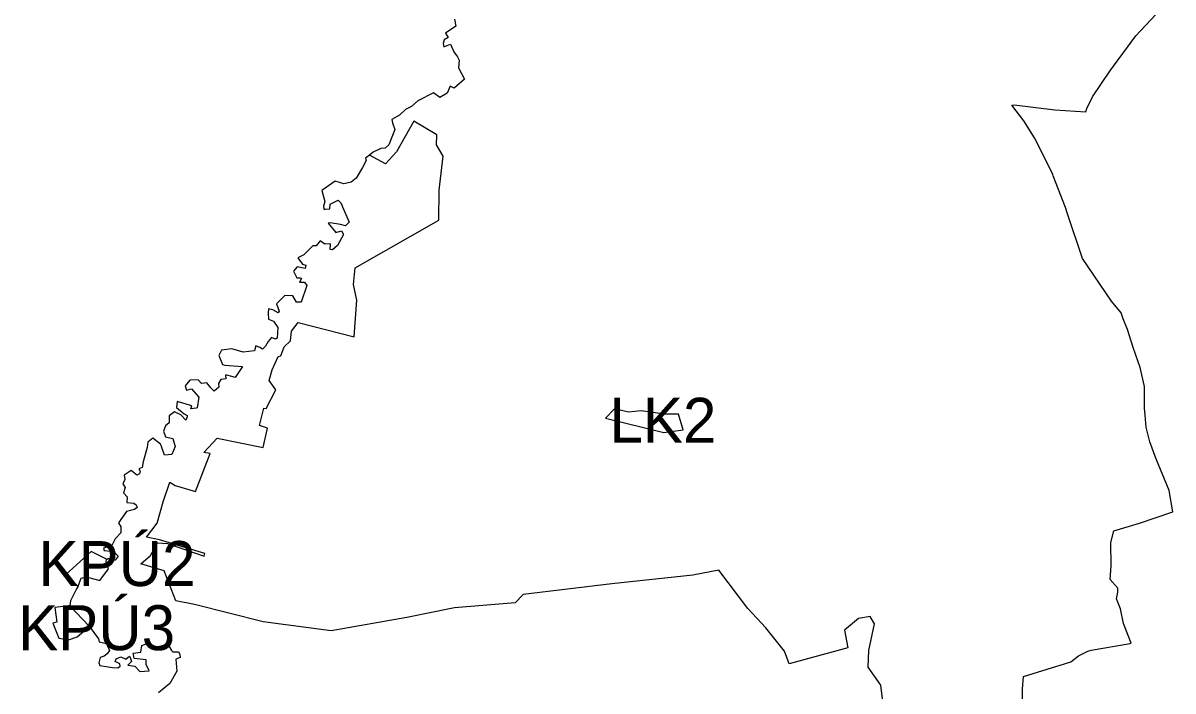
# Model space of a CAD drawing. Extents: x -744334 to -741989, y -1190045 to -1186328.
# Drawn here: x -744127 to -742592, y -1189155 to -1188264 of the extents above; entities that cross this region are included whole.
import ezdxf

# ---------------------------------------------------------------- set-up
doc = ezdxf.new("R2010")
doc.units = 0
for name, color, linetype in [('Hranice parcel', 7, 'Continuous'), ('Parcelní čísla', 7, 'Continuous'), ('Značky budov', 7, 'Continuous')]:
    doc.layers.add(name, color=color, linetype=linetype)

msp = doc.modelspace()

# ---------------------------------------------------------------- linework, layer by layer
at = {"layer": 'Hranice parcel'}
msp.add_line((-744038.9, -1189068.8), (-744064.9, -1189041.5), dxfattribs=at)
for points in [[(-743685.4, -1188682.5), (-743681.6, -1188633.9), (-743686.2, -1188613), (-743684.2, -1188590.5), (-743572.5, -1188526.8), (-743572, -1188487), (-743566.4, -1188441.6), (-743575.6, -1188426.2), (-743575, -1188413), (-743605.6, -1188394.6), (-743628.6, -1188435.9), (-743643.4, -1188451.8), (-743665, -1188440.3)], [(-742977.4, -1189187.5), (-742982, -1189147.7), (-742998.9, -1189123.5), (-742998.4, -1189101.1), (-742990.6, -1189065.5), (-742996.6, -1189055.9), (-743012.1, -1189058.4), (-743030.7, -1189074.1), (-743026.4, -1189097.8), (-743104.8, -1189118.8), (-743110.8, -1189101.9), (-743135.7, -1189071), (-743159.9, -1189045.2), (-743198.6, -1188994.2), (-743233.3, -1189000.5), (-743341.5, -1189012.1), (-743459.5, -1189026.3), (-743470.5, -1189037.6), (-743551.5, -1189044.5), (-743615, -1189057.1), (-743715.9, -1189075), (-743806.8, -1189063.1), (-743898.4, -1189039.9), (-743923.3, -1189034.9), (-743939.1, -1188994.9), (-743970.2, -1188985.6), (-743957.3, -1188974.4), (-743947.7, -1188957.5), (-743934.5, -1188958.5), (-743885.6, -1188975.4), (-743884.9, -1188971.7), (-743945.1, -1188953.5), (-743962.6, -1188949.9), (-743948.4, -1188931.3), (-743940.5, -1188902.9), (-743931.2, -1188876.4), (-743924.2, -1188881), (-743897.1, -1188889), (-743877.6, -1188838.4), (-743885.9, -1188837), (-743868, -1188817.8), (-743806.8, -1188830.4), (-743801.2, -1188804.3), (-743811.8, -1188801), (-743805.8, -1188777.8), (-743802.9, -1188778.1), (-743790, -1188753.3), (-743798.9, -1188741.1), (-743794.9, -1188726.8), (-743787, -1188709), (-743783.3, -1188708), (-743778.7, -1188696.1), (-743770.5, -1188687.8), (-743769.1, -1188675.2), (-743760.2, -1188663.6), (-743685.4, -1188682.5)], [(-744053.9, -1189015.5), (-744049.6, -1189004.7), (-744042.9, -1189002.8), (-744025, -1189007.6), (-744013.5, -1188992.2), (-744016.2, -1188983), (-744016, -1188979.4)]]:
    msp.add_lwpolyline(points, dxfattribs=at)
msp.add_lwpolyline([(-743349.7, -1188791.2), (-743271.8, -1188810.2), (-743245.9, -1188806.7), (-743252.5, -1188786), (-743270.8, -1188786), (-743302.1, -1188781.6), (-743319.1, -1188783), (-743337.6, -1188778.6)], close=True, dxfattribs=at)
at = {"layer": 'Parcelní čísla'}
for p, q in [((-742641.8, -1188280.9), (-742609, -1188245.6)), ((-743551.5, -1188258.5), (-743549.5, -1188268)), ((-743549.5, -1188268), (-743563.4, -1188277.3)), ((-743563.4, -1188277.3), (-743559.9, -1188283.1)), ((-742676.3, -1188328.1), (-742641.8, -1188280.9)), ((-743565.1, -1188286.3), (-743566.3, -1188291.3)), ((-743566.3, -1188291.3), (-743565.6, -1188295.6)), ((-743565.6, -1188295.6), (-743556.8, -1188292.2)), ((-743559.9, -1188283.1), (-743565.1, -1188286.3)), ((-743556.8, -1188292.2), (-743552.1, -1188302.5)), ((-743552.1, -1188302.5), (-743547.5, -1188309.1)), ((-743547.5, -1188309.1), (-743545.2, -1188313.2)), ((-743545.2, -1188313.2), (-743546.1, -1188323.8)), ((-743546.1, -1188323.8), (-743538.2, -1188338.8)), ((-743538.2, -1188338.8), (-743551.8, -1188350.7)), ((-742687.6, -1188344.7), (-742676.3, -1188328.1)), ((-743579.3, -1188357.1), (-743600.2, -1188367.6)), ((-743571, -1188363.3), (-743579.3, -1188357.1)), ((-743561.3, -1188357.3), (-743571, -1188363.3)), ((-743557.2, -1188348.3), (-743561.3, -1188357.3)), ((-743551.8, -1188350.7), (-743557.2, -1188348.3)), ((-742699.5, -1188362.4), (-742687.6, -1188344.7)), ((-743600.2, -1188367.6), (-743608.6, -1188375.1)), ((-742807.1, -1188373.3), (-742804.2, -1188372.9)), ((-742804.2, -1188372.9), (-742749.7, -1188379.6)), ((-742707, -1188378), (-742699.5, -1188362.4)), ((-743625, -1188386.9), (-743634.9, -1188392.5)), ((-743617, -1188379.1), (-743625, -1188386.9)), ((-743608.6, -1188375.1), (-743617, -1188379.1)), ((-742791.1, -1188394.5), (-742807.1, -1188373.3)), ((-742749.7, -1188379.6), (-742708.4, -1188382.2)), ((-742708.4, -1188382.2), (-742707, -1188378)), ((-743634.9, -1188392.5), (-743634.3, -1188397)), ((-743634.3, -1188397), (-743631.1, -1188405.8)), ((-742777.2, -1188417.2), (-742791.1, -1188394.5)), ((-743631.1, -1188405.8), (-743639, -1188426.6)), ((-742768.4, -1188433.4), (-742777.2, -1188417.2)), ((-743649.7, -1188431.1), (-743659.8, -1188436.3)), ((-743643.9, -1188430.7), (-743649.7, -1188431.1)), ((-743639, -1188426.6), (-743643.9, -1188430.7)), ((-742752.7, -1188466.2), (-742768.4, -1188433.4)), ((-743669.5, -1188447.4), (-743674, -1188456.7)), ((-743665, -1188440.3), (-743670.1, -1188444.2)), ((-743670.1, -1188444.2), (-743669.5, -1188447.4)), ((-743659.8, -1188436.3), (-743665, -1188440.3)), ((-743674, -1188456.7), (-743682.6, -1188470.8)), ((-743710.9, -1188474.8), (-743728.4, -1188487.4)), ((-743699.2, -1188478.5), (-743710.9, -1188474.8)), ((-743689.2, -1188476.2), (-743699.2, -1188478.5)), ((-743682.6, -1188470.8), (-743689.2, -1188476.2)), ((-742752.1, -1188467.6), (-742752.7, -1188466.2)), ((-742735.7, -1188510.2), (-742752.1, -1188467.6)), ((-743728.4, -1188487.4), (-743724.3, -1188502)), ((-743724.3, -1188502), (-743726.3, -1188508.1)), ((-743726.3, -1188508.1), (-743725.7, -1188512.4)), ((-743717.7, -1188512), (-743717.2, -1188505.6)), ((-743717.2, -1188505.6), (-743706.6, -1188500.1)), ((-743706.6, -1188500.1), (-743703, -1188503.7)), ((-743703, -1188503.7), (-743699.4, -1188512.3)), ((-742733, -1188518.4), (-742735.7, -1188510.2)), ((-743725.7, -1188512.4), (-743723.7, -1188512.4)), ((-743723.7, -1188512.4), (-743717.7, -1188512)), ((-743699.4, -1188512.3), (-743692, -1188529.6)), ((-742712.8, -1188578.2), (-742733, -1188518.4)), ((-743717.4, -1188530.5), (-743720.2, -1188531)), ((-743720.2, -1188531), (-743709.6, -1188543.5)), ((-743703.4, -1188532.9), (-743717.4, -1188530.5)), ((-743709.6, -1188543.5), (-743702.1, -1188541)), ((-743696.9, -1188534.4), (-743703.4, -1188532.9)), ((-743702.1, -1188541), (-743699.4, -1188545.9)), ((-743692, -1188529.6), (-743696.9, -1188534.4)), ((-743730.5, -1188554.4), (-743736.2, -1188561.2)), ((-743724.4, -1188559.1), (-743730.5, -1188554.4)), ((-743699.4, -1188545.9), (-743707.6, -1188560.9)), ((-743745.2, -1188566), (-743752.6, -1188573)), ((-743740.5, -1188561.4), (-743745.2, -1188566)), ((-743736.2, -1188561.2), (-743740.5, -1188561.4)), ((-743716.8, -1188558.3), (-743724.4, -1188559.1)), ((-743717.2, -1188566.1), (-743716.8, -1188558.3)), ((-743714.1, -1188566.3), (-743717.2, -1188566.1)), ((-743707.6, -1188560.9), (-743714.1, -1188566.3)), ((-743752.6, -1188573), (-743760.6, -1188577.4)), ((-743760.6, -1188577.4), (-743754.5, -1188585.6)), ((-743754.5, -1188585.6), (-743749.8, -1188587.2)), ((-743749.8, -1188587.2), (-743750.7, -1188591.5)), ((-742674.4, -1188635), (-742712.8, -1188578.2)), ((-743761.5, -1188589.2), (-743766.4, -1188595)), ((-743766.4, -1188595), (-743761.9, -1188603.8)), ((-743750.7, -1188591.5), (-743761.5, -1188589.2)), ((-743761.9, -1188603.8), (-743757.3, -1188604)), ((-743755.5, -1188604.8), (-743758.1, -1188609.8)), ((-743758.1, -1188609.8), (-743751.7, -1188609.5)), ((-743757.3, -1188604), (-743755.5, -1188604.8)), ((-743748.5, -1188614), (-743755.9, -1188636.5)), ((-743751.7, -1188609.5), (-743748.5, -1188614)), ((-743778, -1188627.4), (-743789.2, -1188638.8)), ((-743767.2, -1188628.1), (-743778, -1188627.4)), ((-743762.4, -1188636.3), (-743767.2, -1188628.1)), ((-743799.6, -1188645.2), (-743800.1, -1188651.1)), ((-743794, -1188646.7), (-743799.6, -1188645.2)), ((-743786.9, -1188650.4), (-743794, -1188646.7)), ((-743789.2, -1188638.8), (-743785.6, -1188648.4)), ((-743785.6, -1188648.4), (-743786.9, -1188650.4)), ((-743755.9, -1188636.5), (-743762.4, -1188636.3)), ((-742661.4, -1188650.8), (-742674.4, -1188635)), ((-743800.1, -1188651.1), (-743799.7, -1188659.2)), ((-743799.7, -1188659.2), (-743793.2, -1188661.9)), ((-743793.2, -1188661.9), (-743787.2, -1188670.2)), ((-742658.9, -1188658.4), (-742661.4, -1188650.8)), ((-742652.8, -1188672.8), (-742658.9, -1188658.4)), ((-743787.2, -1188670.2), (-743788.1, -1188684.4)), ((-742645.3, -1188697), (-742652.8, -1188672.8)), ((-743816.4, -1188694.6), (-743818.5, -1188701.5)), ((-743811.4, -1188696.7), (-743816.4, -1188694.6)), ((-743803.5, -1188695.1), (-743807.8, -1188699.1)), ((-743800.2, -1188688.8), (-743803.5, -1188695.1)), ((-743795.8, -1188683.6), (-743800.2, -1188688.8)), ((-743790.3, -1188685.8), (-743795.8, -1188683.6)), ((-743788.1, -1188684.4), (-743790.3, -1188685.8)), ((-743862.5, -1188700.4), (-743866.1, -1188707.4)), ((-743866.1, -1188707.4), (-743861, -1188719.6)), ((-743848.8, -1188698.5), (-743862.5, -1188700.4)), ((-743833.3, -1188703.2), (-743848.8, -1188698.5)), ((-743818.5, -1188701.5), (-743833.3, -1188703.2)), ((-743807.8, -1188699.1), (-743811.4, -1188696.7)), ((-742635.9, -1188723.7), (-742645.3, -1188697)), ((-743861, -1188719.6), (-743858.1, -1188720.5)), ((-743858.1, -1188720.5), (-743834.5, -1188722.1)), ((-743834.5, -1188722.1), (-743844.1, -1188737.1)), ((-742630.3, -1188749), (-742635.9, -1188723.7)), ((-743904.8, -1188740.4), (-743910.8, -1188748)), ((-743893.8, -1188740), (-743904.8, -1188740.4)), ((-743889, -1188744.7), (-743893.8, -1188740)), ((-743863.2, -1188739.7), (-743866.5, -1188745)), ((-743856.5, -1188738.5), (-743863.2, -1188739.7)), ((-743855.3, -1188733.9), (-743857.2, -1188733.8)), ((-743857.2, -1188733.8), (-743856.5, -1188738.5)), ((-743848.8, -1188735.7), (-743855.3, -1188733.9)), ((-743844.1, -1188737.1), (-743848.8, -1188735.7)), ((-743910.8, -1188748), (-743909.3, -1188753.6)), ((-743909.3, -1188753.6), (-743902.5, -1188752.1)), ((-743902.5, -1188752.1), (-743892.6, -1188763.2)), ((-743881.9, -1188744.1), (-743889, -1188744.7)), ((-743876.5, -1188750.9), (-743881.9, -1188744.1)), ((-743872.4, -1188755.2), (-743876.5, -1188750.9)), ((-743865.9, -1188750), (-743872.4, -1188755.2)), ((-743866.5, -1188745), (-743865.9, -1188750)), ((-742630.1, -1188769.5), (-742630.3, -1188749)), ((-743921.4, -1188768.9), (-743922.3, -1188777.1)), ((-743902.1, -1188774.5), (-743921.4, -1188768.9)), ((-743892.6, -1188763.2), (-743894.9, -1188777.5)), ((-742630, -1188777.8), (-742630.1, -1188769.5)), ((-743925, -1188782.7), (-743932.2, -1188787.9)), ((-743916.9, -1188786.8), (-743925, -1188782.7)), ((-743922.3, -1188777.1), (-743912.4, -1188785.2)), ((-743909.9, -1188794), (-743916.9, -1188786.8)), ((-743912.4, -1188785.2), (-743908.2, -1188787.5)), ((-743908.2, -1188787.5), (-743908.1, -1188789.5)), ((-743903.5, -1188778.8), (-743902.1, -1188774.5)), ((-743896.1, -1188777.7), (-743903.5, -1188778.8)), ((-743894.9, -1188777.5), (-743896.1, -1188777.7)), ((-742629.1, -1188787.3), (-742630, -1188777.8)), ((-742628, -1188803.2), (-742629.1, -1188787.3)), ((-743937, -1188801.2), (-743940, -1188808.4)), ((-743932.1, -1188797.5), (-743937, -1188801.2)), ((-743932.2, -1188787.9), (-743932.1, -1188797.5)), ((-743908.1, -1188789.5), (-743909.9, -1188794)), ((-743953.9, -1188817.9), (-743960.9, -1188823)), ((-743943.7, -1188825.9), (-743953.9, -1188817.9)), ((-743940, -1188808.4), (-743937.2, -1188816.3)), ((-743937.2, -1188816.3), (-743933.6, -1188817.1)), ((-743933.6, -1188817.1), (-743927.5, -1188818.5)), ((-743927.5, -1188818.5), (-743924.1, -1188828.8)), ((-742623.3, -1188822.7), (-742628, -1188803.2)), ((-743961.8, -1188830.2), (-743963.4, -1188836.6)), ((-743960.9, -1188823), (-743961.8, -1188830.2)), ((-743943, -1188827.8), (-743943.7, -1188825.9)), ((-743938.4, -1188840.4), (-743943, -1188827.8)), ((-743924.1, -1188828.8), (-743928.7, -1188839.7)), ((-742615.2, -1188844.5), (-742623.3, -1188822.7)), ((-743963.4, -1188836.6), (-743967.1, -1188849.3)), ((-743928.7, -1188839.7), (-743938.4, -1188840.4)), ((-742597.4, -1188887.6), (-742615.2, -1188844.5)), ((-743983.2, -1188860.9), (-743992.3, -1188867.3)), ((-743975.4, -1188867.3), (-743983.2, -1188860.9)), ((-743968.3, -1188857), (-743972.7, -1188858.7)), ((-743972.7, -1188858.7), (-743970.8, -1188862.1)), ((-743970.8, -1188862.1), (-743972, -1188865.5)), ((-743967.1, -1188849.3), (-743968.3, -1188857)), ((-743991.3, -1188872.9), (-743994, -1188878.9)), ((-743994, -1188878.9), (-743990.9, -1188883.5)), ((-743992.3, -1188867.3), (-743991.3, -1188872.9)), ((-743972, -1188865.5), (-743975.4, -1188867.3)), ((-743990.9, -1188883.5), (-743993.3, -1188890.9)), ((-743993.3, -1188890.9), (-743988.2, -1188896.1)), ((-742592.2, -1188916), (-742597.4, -1188887.6)), ((-743988.2, -1188896.1), (-743988.9, -1188903.7)), ((-743988.9, -1188903.7), (-743979.4, -1188904.7)), ((-743979.4, -1188904.7), (-743976.5, -1188907)), ((-743974.9, -1188910.4), (-743978.7, -1188913)), ((-743976.5, -1188907), (-743974.9, -1188910.4)), ((-743989.4, -1188915.9), (-743999.8, -1188930.9)), ((-743978.7, -1188913), (-743989.4, -1188915.9)), ((-742637, -1188931.4), (-742592.2, -1188916)), ((-743999.8, -1188930.9), (-743996.9, -1188936.1)), ((-743996.9, -1188936.1), (-743996.8, -1188944.1)), ((-742671.2, -1188941.5), (-742637, -1188931.4)), ((-744004.4, -1188952), (-744008.4, -1188960.1)), ((-743996.8, -1188944.1), (-744004.4, -1188952)), ((-742675.3, -1188956.9), (-742671.2, -1188941.5)), ((-744036.5, -1188969.1), (-744070.6, -1189000.1)), ((-744016.8, -1188979), (-744036.5, -1188969.1)), ((-744008.4, -1188960.1), (-744019.8, -1188964.5)), ((-744019.8, -1188964.5), (-744019, -1188967.7)), ((-744019, -1188967.7), (-744006, -1188968.9)), ((-744006, -1188968.9), (-744000.6, -1188975.3)), ((-742674.5, -1188988.2), (-742675.3, -1188956.9)), ((-744015.1, -1188979.8), (-744016.8, -1188979)), ((-744013.8, -1188978.5), (-744015.1, -1188979.8)), ((-744009.3, -1188980.9), (-744013.8, -1188978.5)), ((-744004.2, -1188980.6), (-744009.3, -1188980.9)), ((-744000.6, -1188975.3), (-744004.2, -1188980.6)), ((-744070.6, -1189000.1), (-744054.9, -1189014.6)), ((-742675.9, -1189006.3), (-742674.5, -1188988.2)), ((-744053.9, -1189015.5), (-744055.8, -1189019)), ((-744054.9, -1189014.6), (-744053.9, -1189015.5)), ((-742665.9, -1189017.9), (-742675.9, -1189006.3)), ((-742665.9, -1189023.5), (-742665.9, -1189017.9)), ((-744055.8, -1189019), (-744064, -1189035.1)), ((-742667.6, -1189032.2), (-742665.9, -1189023.5)), ((-742662.1, -1189045.5), (-742667.6, -1189032.2)), ((-744066.5, -1189041.7), (-744084.9, -1189043.8)), ((-744084.9, -1189043.8), (-744082.4, -1189063.2)), ((-744064.9, -1189041.5), (-744066.5, -1189041.7)), ((-744064, -1189035.1), (-744064.9, -1189041.5)), ((-742658.4, -1189065.4), (-742662.1, -1189045.5)), ((-744082.4, -1189063.2), (-744087.5, -1189064.9)), ((-744087.5, -1189064.9), (-744079.4, -1189084.8)), ((-744055.1, -1189083.1), (-744043.3, -1189072.6)), ((-744043.3, -1189072.6), (-744040.4, -1189070)), ((-744040.4, -1189070), (-744038.9, -1189068.8)), ((-744038.9, -1189068.8), (-744026.5, -1189085.7)), ((-742648.1, -1189091.5), (-742658.4, -1189065.4)), ((-744079.4, -1189084.8), (-744066.5, -1189086.8)), ((-744066.5, -1189086.8), (-744055.1, -1189083.1)), ((-744026.5, -1189085.7), (-744025.8, -1189089.8)), ((-744025.8, -1189089.8), (-744016.1, -1189092)), ((-744016.1, -1189092), (-744011.9, -1189101.2)), ((-743970, -1189103.3), (-743968.8, -1189094.6)), ((-743968.8, -1189094.6), (-743958.7, -1189090.4)), ((-743958.7, -1189090.4), (-743951.4, -1189097)), ((-743951.4, -1189097), (-743937.9, -1189093.7)), ((-743937.9, -1189093.7), (-743932.1, -1189095.8)), ((-742701.3, -1189100.6), (-742649.2, -1189091.7)), ((-742649.2, -1189091.7), (-742648.1, -1189091.5)), ((-744019, -1189108.9), (-744024.5, -1189110.7)), ((-744015.1, -1189105.8), (-744019, -1189108.9)), ((-744011.9, -1189101.2), (-744015.1, -1189105.8)), ((-744002.9, -1189112.4), (-743996.9, -1189109.5)), ((-743996.9, -1189109.5), (-743990.2, -1189112.6)), ((-743990.2, -1189112.6), (-743985.2, -1189108.8)), ((-743985.2, -1189108.8), (-743984.5, -1189110.5)), ((-743980.3, -1189104.6), (-743970, -1189103.3)), ((-743979.7, -1189106.7), (-743980.3, -1189104.6)), ((-743979, -1189111.7), (-743979.7, -1189106.7)), ((-743932.1, -1189095.8), (-743929.4, -1189101.1)), ((-743929.4, -1189101.1), (-743927.5, -1189103.1)), ((-743927.5, -1189103.1), (-743919.9, -1189102.8)), ((-743919.9, -1189102.8), (-743917.9, -1189106.1)), ((-743917.9, -1189106.1), (-743917.6, -1189110.5)), ((-742728.6, -1189116.4), (-742718.1, -1189108.2)), ((-742718.1, -1189108.2), (-742705.9, -1189102)), ((-742705.9, -1189102), (-742701.3, -1189100.6)), ((-744024.5, -1189110.7), (-744026.4, -1189117.8)), ((-744026.4, -1189117.8), (-744024.9, -1189121.2)), ((-744024.9, -1189121.2), (-744007.8, -1189124)), ((-744007.8, -1189124), (-744001, -1189124.5)), ((-744004.6, -1189115.8), (-744002.9, -1189112.4)), ((-743998, -1189119.1), (-744004.6, -1189115.8)), ((-744001, -1189124.5), (-743997.9, -1189122.2)), ((-743997.9, -1189122.2), (-743998, -1189119.1)), ((-743982.4, -1189115.8), (-743987.6, -1189120.8)), ((-743987.6, -1189120.8), (-743978.1, -1189122.1)), ((-743984.5, -1189110.5), (-743982.4, -1189115.8)), ((-743963.1, -1189113.6), (-743979, -1189111.7)), ((-743978.1, -1189122.1), (-743971.3, -1189129.2)), ((-743963.1, -1189119.8), (-743963.1, -1189113.6)), ((-743958.8, -1189128.5), (-743963.1, -1189119.8)), ((-743917.6, -1189110.5), (-743923.3, -1189112.6)), ((-743923.3, -1189112.6), (-743922.1, -1189128.7)), ((-742791.7, -1189135.8), (-742747.1, -1189122.2)), ((-742747.1, -1189122.2), (-742744, -1189121.3)), ((-742744, -1189121.3), (-742728.6, -1189116.4)), ((-743971.3, -1189129.2), (-743958.8, -1189128.5)), ((-743922.1, -1189128.7), (-743931.3, -1189145.2)), ((-742792.9, -1189152.7), (-742791.7, -1189135.8)), ((-743931.3, -1189145.2), (-743946.4, -1189157.9)), ((-742792.9, -1189178.2), (-742792.9, -1189152.7))]:
    msp.add_line(p, q, dxfattribs=at)

# ---------------------------------------------------------------- texts
at = {"layer": 'Značky budov'}
for s, p in [('LK2', (-743344.5, -1188824)), ('KPÚ2', (-744106.7, -1189015.2)), ('KPÚ3', (-744134, -1189100.8))]:
    msp.add_text(s, height=60, dxfattribs=at).set_placement(p)

doc.saveas('drawing.dxf')
